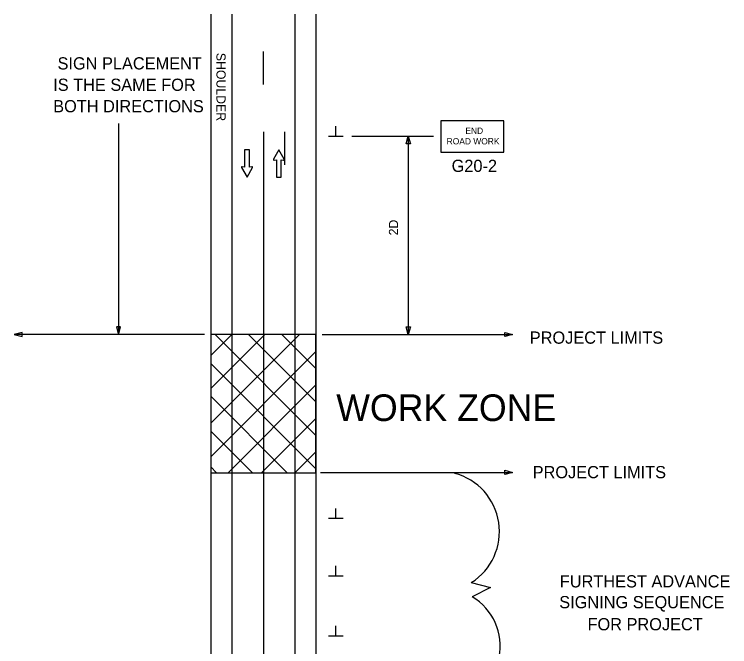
# Model space of a CAD drawing. Extents: x 16734 to 18468, y 5860 to 6911.
# Drawn here: x 16785 to 17329, y 6361 to 6843 of the extents above; entities that cross this region are included whole.
import ezdxf

# ---------------------------------------------------------------- set-up
doc = ezdxf.new("R2010")
doc.units = 0
for name, color, linetype in [('MT_SCRATCH_LEVEL_E', 7, 'Continuous'), ('PAVT_EDGE_EX', 7, 'Continuous'), ('TRAFFIC_SIGNS_PR', 7, 'Continuous'), ('TYPICAL_TEXT_DIMEN_PR', 7, 'Continuous')]:
    doc.layers.add(name, color=color, linetype=linetype)

msp = doc.modelspace()

# ---------------------------------------------------------------- linework, layer by layer
at = {"layer": 'MT_SCRATCH_LEVEL_E'}
for p, q in [((16963.595, 6739.487), (16959.853, 6739.487)), ((16959.853, 6739.487), (16959.853, 6726.229)), ((16963.595, 6739.487), (16959.853, 6739.487)), ((16959.853, 6739.487), (16959.853, 6726.229)), ((16963.595, 6726.229), (16963.595, 6739.487)), ((16963.595, 6726.229), (16963.595, 6739.487)), ((16985.957, 6739.486), (16981.833, 6732.252)), ((16985.957, 6739.486), (16981.833, 6732.252)), ((16990.091, 6732.237), (16985.957, 6739.486)), ((16990.091, 6732.237), (16985.957, 6739.486)), ((16982.314, 6731.568), (16984.091, 6731.88)), ((16982.314, 6731.568), (16984.091, 6731.88)), ((16984.091, 6731.88), (16984.067, 6718.622)), ((16984.091, 6731.88), (16984.067, 6718.622)), ((16987.809, 6718.616), (16987.833, 6731.874)), ((16987.809, 6718.616), (16987.833, 6731.874)), ((16987.833, 6731.874), (16989.611, 6731.554)), ((16987.833, 6731.874), (16989.611, 6731.554)), ((16957.596, 6725.861), (16961.743, 6718.62)), ((16957.596, 6725.861), (16961.743, 6718.62)), ((16959.853, 6726.229), (16958.075, 6726.545)), ((16959.853, 6726.229), (16958.075, 6726.545)), ((16961.743, 6718.62), (16965.854, 6725.861)), ((16961.743, 6718.62), (16965.854, 6725.861)), ((16965.372, 6726.545), (16963.595, 6726.229)), ((16965.372, 6726.545), (16963.595, 6726.229)), ((16984.067, 6718.622), (16987.809, 6718.616)), ((16984.067, 6718.622), (16987.809, 6718.616))]:
    msp.add_line(p, q, dxfattribs=at)
for centre, start, end in [((16982.24, 6732.028), 150.3205, 279.85947), ((16982.24, 6732.028), 150.3205, 279.85947), ((16989.681, 6732.015), 259.93186, 29.66878), ((16989.681, 6732.015), 259.93186, 29.66878), ((16958.006, 6726.084), 80.03619, 209.77312), ((16958.006, 6726.084), 80.03619, 209.77312), ((16965.446, 6726.085), 330.42484, 99.96381), ((16965.446, 6726.085), 330.42484, 99.96381)]:
    msp.add_arc(centre, 0.463, start, end, dxfattribs=at)
at = {"layer": 'PAVT_EDGE_EX'}
for p, q in [((16934.188, 6842.558), (16934.188, 5999.579)), ((16950.188, 6842.558), (16950.188, 5999.579)), ((16998.188, 6842.558), (16998.188, 5999.579)), ((17014.188, 6842.558), (17014.188, 5999.579)), ((16974.188, 6752.987), (16974.188, 5999.579)), ((16974.188, 6752.987), (16974.188, 5999.579)), ((17014.188, 6598.737), (16934.188, 6598.737)), ((16934.349, 6531.413), (17001.673, 6598.737)), ((16934.367, 6583.029), (16949.87, 6598.532)), ((16934.445, 6558.027), (16974.922, 6598.504)), ((17014.188, 6521.977), (16937.23, 6598.935)), ((17014.188, 6547.433), (16962.642, 6598.979)), ((17014.188, 6572.888), (16988.481, 6598.595)), ((16998.188, 6599.208), (16998.188, 6493.429)), ((17014.188, 6598.344), (17013.795, 6598.737)), ((17014.188, 6493.429), (17014.188, 6598.737)), ((16934.323, 6505.932), (17014.188, 6585.797)), ((17014.124, 6496.585), (16934.342, 6576.367)), ((16947.431, 6493.584), (17014.188, 6560.341)), ((16992.318, 6493.555), (16934.114, 6551.759)), ((16972.754, 6493.451), (17014.188, 6534.885)), ((16965.839, 6493.49), (16934.306, 6525.023)), ((16998.188, 6493.429), (17014.188, 6509.429)), ((16938.318, 6493.655), (16934.303, 6497.67)), ((16934.188, 6493.429), (17014.159, 6493.429)), ((16998.188, 6493.429), (17014.188, 6493.429)), ((16998.188, 6493.429), (16998.188, 6493.429))]:
    msp.add_line(p, q, dxfattribs=at)
for points in [[(16974.188, 6789.15), (16974.188, 6814.15)], [(16990.188, 6752.987), (16990.188, 6727.987)], [(16974.188, 6652.987), (16974.188, 6627.987)], [(16974.188, 6452.987), (16974.188, 6427.987)]]:
    msp.add_lwpolyline(points, dxfattribs=at)
at = {"layer": 'TRAFFIC_SIGNS_PR'}
msp.add_lwpolyline([(17109.265, 6737.582), (17157.265, 6737.582), (17157.265, 6761.582), (17109.265, 6761.582)], close=True, dxfattribs=at)
at = {"layer": 'TYPICAL_TEXT_DIMEN_PR'}
for p, q in [((16863.848, 6759.42), (16863.848, 6598.889)), ((17029.341, 6749.571), (17029.341, 6757.356)), ((17029.341, 6749.571), (17023.716, 6749.571)), ((17034.966, 6749.571), (17029.341, 6749.571)), ((17041.525, 6749.778), (17103.839, 6749.778)), ((17082.967, 6744.016), (17084.538, 6749.878)), ((17084.528, 6749.673), (17084.528, 6598.889)), ((17084.538, 6749.878), (17086.109, 6744.016)), ((17084.538, 6744.016), (17082.967, 6744.016)), ((17086.109, 6744.016), (17084.538, 6744.016)), ((16863.837, 6604.574), (16862.266, 6604.574)), ((16862.266, 6604.574), (16863.837, 6598.712)), ((16863.837, 6598.712), (16865.408, 6604.574)), ((16865.408, 6604.574), (16863.837, 6604.574)), ((17084.539, 6598.712), (17082.968, 6604.574)), ((17082.968, 6604.574), (17084.539, 6604.574)), ((17084.539, 6604.574), (17086.11, 6604.574)), ((17086.11, 6604.574), (17084.539, 6598.712)), ((16790.368, 6600.296), (16784.506, 6598.725)), ((16929.31, 6598.725), (16784.506, 6598.725)), ((16784.506, 6598.725), (16790.368, 6597.154)), ((16790.368, 6598.725), (16790.368, 6600.296)), ((16790.368, 6597.154), (16790.368, 6598.725)), ((17019.066, 6598.725), (17163.87, 6598.725)), ((17158.008, 6598.725), (17158.008, 6600.296)), ((17158.008, 6600.296), (17163.87, 6598.725)), ((17163.87, 6598.725), (17158.008, 6597.154)), ((17158.008, 6597.154), (17158.008, 6598.725)), ((17158.008, 6493.824), (17158.008, 6495.395)), ((17158.008, 6495.395), (17163.87, 6493.824)), ((17017.581, 6493.824), (17163.87, 6493.824)), ((17163.87, 6493.824), (17158.008, 6492.253)), ((17158.008, 6492.253), (17158.008, 6493.824)), ((17029.384, 6458.635), (17029.384, 6466.42)), ((17029.384, 6458.635), (17023.759, 6458.635)), ((17035.009, 6458.635), (17029.384, 6458.635)), ((17029.36, 6414.813), (17029.36, 6422.598)), ((17029.36, 6414.813), (17023.735, 6414.813)), ((17034.985, 6414.813), (17029.36, 6414.813)), ((17132.538, 6409.978), (17147.18, 6406.118)), ((17147.18, 6406.118), (17133.153, 6399.106)), ((17029.334, 6369.212), (17029.334, 6376.997)), ((17029.334, 6369.212), (17023.709, 6369.212)), ((17034.959, 6369.212), (17029.334, 6369.212))]:
    msp.add_line(p, q, dxfattribs=at)
for centre, radius, start, end in [((17108.148, 6448.747), 45.823, 302.15629, 75.25172), ((17111.587, 6361.896), 42.925, 276.33749, 59.97889)]:
    msp.add_arc(centre, radius, start, end, dxfattribs=at)

# ---------------------------------------------------------------- texts
at = {"layer": 'TRAFFIC_SIGNS_PR'}
for s, height, p in [('SIGN PLACEMENT', 9.3, (16817.444, 6800.566)), ('IS THE SAME FOR', 9.3, (16814.126, 6784.266)), ('BOTH DIRECTIONS', 9.3, (16814.105, 6767.966)), ('END', 4.789, (17128.016, 6751.492)), ('ROAD WORK', 4.789, (17113.777, 6743.51)), ('G20-2', 9.3, (17117.55, 6722.558)), ('PROJECT LIMITS', 9.3, (17177.077, 6591.769)), ('PROJECT LIMITS', 9.3, (17179.265, 6489.349)), ('FURTHEST ADVANCE', 9.3, (17199.942, 6406.206)), ('SIGNING SEQUENCE', 9.3, (17199.509, 6390.371)), ('FOR PROJECT', 9.3, (17221.038, 6373.559))]:
    msp.add_text(s, height=height, dxfattribs=at).set_placement(p)
at = {"layer": 'TYPICAL_TEXT_DIMEN_PR'}
for s, rotation, p in [('SHOULDER', 270, (16938.445, 6813.229)), ('2D', 90, (17076.802, 6674.255))]:
    msp.add_text(s, height=7, rotation=rotation, dxfattribs=at).set_placement(p)
msp.add_text('WORK ZONE', height=20.309, dxfattribs=at).set_placement((17029.697, 6532.881))

doc.saveas('drawing.dxf')
